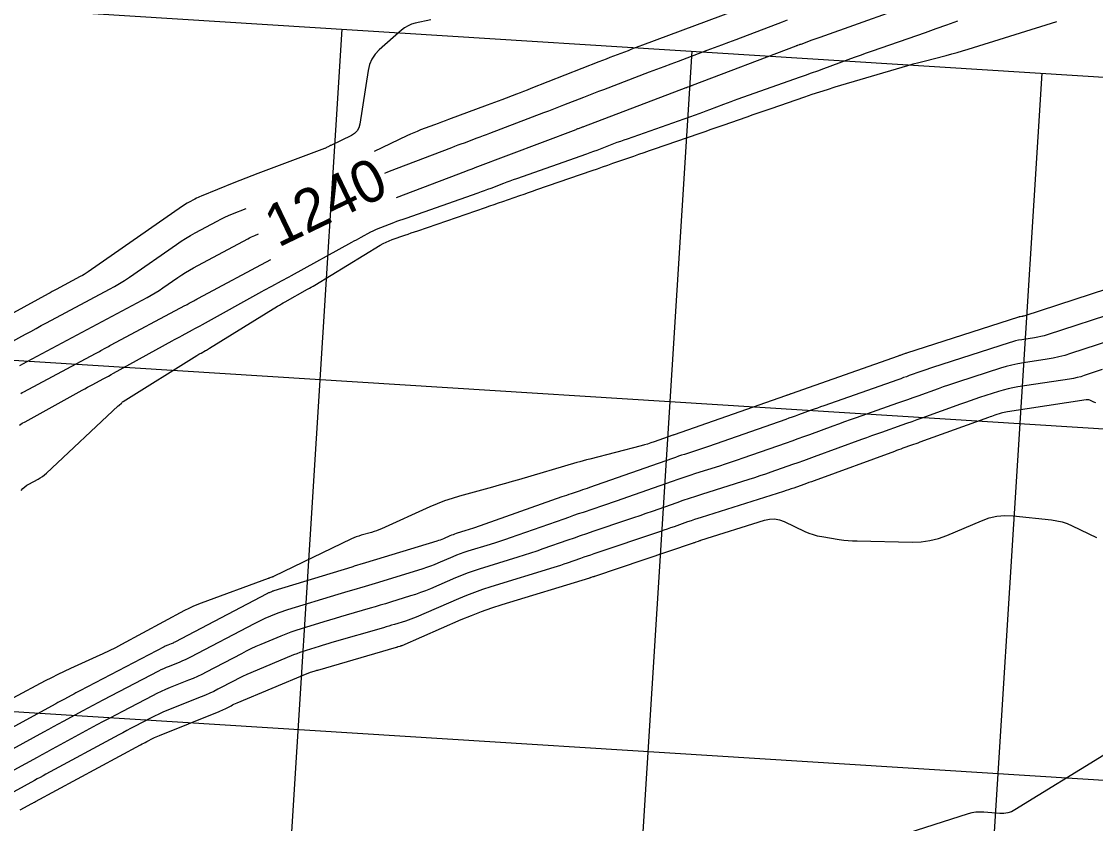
# Model space of a CAD drawing. Extents: x 658976 to 668721, y 639543 to 647196.
# Drawn here: x 662439.7 to 662592.9, y 641935.7 to 642050 of the extents above; entities that cross this region are included whole.
import ezdxf

# ---------------------------------------------------------------- set-up
doc = ezdxf.new("R2010")
doc.units = 0
for name, color, linetype in [('Ex_Contour Labels', 7, 'Continuous'), ('Ex_Major Contours', 7, 'Continuous'), ('Ex_Minor Contours', 7, 'Continuous'), ('R_Grid', 7, 'Continuous')]:
    doc.layers.add(name, color=color, linetype=linetype)

msp = doc.modelspace()

# ---------------------------------------------------------------- linework, layer by layer
at = {"layer": 'Ex_Major Contours'}
for points in [[(662491.52, 642028.41), (662491.94, 642028.59), (662492.57, 642028.85), (662493.2, 642029.1), (662501.06, 642032.09), (662501.51, 642032.26), (662501.96, 642032.43), (662502.41, 642032.6), (662502.86, 642032.76), (662504.67, 642033.43), (662505.12, 642033.6), (662505.57, 642033.76), (662506.02, 642033.93), (662506.47, 642034.1), (662514.21, 642037.05), (662514.92, 642037.32), (662515.63, 642037.59), (662516.34, 642037.87), (662517.05, 642038.15), (662519.89, 642039.26), (662520.6, 642039.54), (662521.31, 642039.81), (662522.02, 642040.09), (662522.73, 642040.36), (662529.28, 642042.85), (662530.3, 642043.24), (662531.33, 642043.63), (662532.36, 642044.01), (662533.38, 642044.4), (662537.5, 642045.93), (662538.52, 642046.31), (662539.55, 642046.7), (662540.58, 642047.09), (662541.6, 642047.48), (662548.24, 642050), (662548.92, 642050.26)], [(662439.47, 642001.02), (662439.99, 642001.3), (662440.51, 642001.58), (662457.63, 642010.7), (662458.2, 642011.02), (662458.77, 642011.35), (662459.32, 642011.7), (662459.86, 642012.07), (662462.01, 642013.56), (662462.55, 642013.93), (662463.11, 642014.28), (662463.67, 642014.61), (662464.24, 642014.93), (662471.98, 642019.07), (662472.23, 642019.2), (662472.48, 642019.32), (662472.73, 642019.43), (662472.99, 642019.54), (662473.5, 642019.75)], [(662593.83, 642000.41), (662591.26, 641999.57), (662590.75, 641999.41), (662590.23, 641999.28), (662589.7, 641999.17), (662589.17, 641999.07), (662581.78, 641997.94), (662581.08, 641997.82), (662580.39, 641997.68), (662579.7, 641997.5), (662579.02, 641997.3), (662576.32, 641996.42), (662575.64, 641996.2), (662574.97, 641995.98), (662574.3, 641995.74), (662573.63, 641995.51), (662568.07, 641993.5), (662567.36, 641993.24), (662566.65, 641992.98), (662565.93, 641992.73), (662565.22, 641992.48), (662562.35, 641991.47), (662561.64, 641991.22), (662560.92, 641990.97), (662560.21, 641990.71), (662559.5, 641990.45), (662552.74, 641987.98), (662551.97, 641987.7), (662551.2, 641987.42), (662550.42, 641987.15), (662549.65, 641986.87), (662546.55, 641985.79), (662545.78, 641985.52), (662545, 641985.26), (662544.22, 641985), (662543.44, 641984.75), (662536.68, 641982.62), (662535.8, 641982.33), (662534.91, 641982.04), (662534.03, 641981.74), (662533.15, 641981.44), (662529.63, 641980.2), (662528.75, 641979.89), (662527.87, 641979.59), (662526.99, 641979.28), (662526.1, 641978.99), (662521.16, 641977.32), (662520.27, 641977.02), (662519.38, 641976.71), (662518.5, 641976.4), (662517.61, 641976.09), (662514.06, 641974.85), (662513.18, 641974.54), (662512.28, 641974.24), (662511.39, 641973.95), (662510.49, 641973.67), (662504.99, 641971.99), (662504.13, 641971.71), (662503.28, 641971.41), (662502.43, 641971.09), (662501.6, 641970.74), (662498.01, 641969.19), (662497.32, 641968.9), (662496.62, 641968.63), (662495.91, 641968.38), (662495.19, 641968.15), (662492.32, 641967.27), (662491.6, 641967.05), (662490.87, 641966.83), (662490.15, 641966.62), (662489.43, 641966.41), (662486, 641965.41), (662485.21, 641965.18), (662484.41, 641964.95), (662483.62, 641964.71), (662482.83, 641964.47), (662479.57, 641963.47), (662478.84, 641963.24), (662478.11, 641962.98), (662477.39, 641962.71), (662476.68, 641962.43), (662473.84, 641961.24), (662473.13, 641960.93), (662472.43, 641960.61), (662471.74, 641960.28), (662471.06, 641959.93), (662466.05, 641957.3), (662465.43, 641956.98), (662464.8, 641956.68), (662464.16, 641956.4), (662463.51, 641956.13), (662460.91, 641955.09), (662460.26, 641954.82), (662459.62, 641954.54), (662458.99, 641954.24), (662458.37, 641953.93), (662454.11, 641951.71), (662453.2, 641951.23), (662452.29, 641950.75), (662451.37, 641950.26), (662450.46, 641949.77), (662444.68, 641946.65), (662443.99, 641946.28), (662443.3, 641945.9), (662442.61, 641945.53), (662441.92, 641945.15), (662433.56, 641940.6)]]:
    msp.add_lwpolyline(points, dxfattribs=at)
at = {"layer": 'Ex_Minor Contours'}
for points in [[(662490.02, 642031.53), (662494.72, 642033.78), (662495.2, 642034), (662495.69, 642034.22), (662496.18, 642034.42), (662496.67, 642034.62), (662498.66, 642035.37), (662499.16, 642035.56), (662499.66, 642035.75), (662500.16, 642035.93), (662500.65, 642036.12), (662506.16, 642038.14), (662506.68, 642038.34), (662507.2, 642038.53), (662507.72, 642038.72), (662508.24, 642038.92), (662510.32, 642039.71), (662510.84, 642039.91), (662511.36, 642040.11), (662511.88, 642040.31), (662512.4, 642040.52), (662522.09, 642044.33), (662522.61, 642044.53), (662523.13, 642044.73), (662523.65, 642044.93), (662524.16, 642045.13), (662526.24, 642045.92), (662526.76, 642046.12), (662527.28, 642046.31), (662527.8, 642046.51), (662528.32, 642046.7), (662543.14, 642052.23)], [(662493.18, 642024.97), (662503.07, 642028.72), (662503.18, 642028.76), (662503.29, 642028.81), (662503.41, 642028.85), (662503.52, 642028.89), (662503.97, 642029.05), (662504.08, 642029.09), (662504.2, 642029.13), (662504.31, 642029.17), (662504.42, 642029.21), (662518.78, 642034.66), (662518.87, 642034.7), (662518.96, 642034.73), (662519.06, 642034.77), (662519.15, 642034.8), (662519.53, 642034.93), (662519.63, 642034.97), (662519.72, 642035), (662519.81, 642035.04), (662519.91, 642035.07), (662534.48, 642040.61), (662534.56, 642040.64), (662534.63, 642040.67), (662534.71, 642040.7), (662534.78, 642040.72), (662535.09, 642040.83), (662535.17, 642040.86), (662535.24, 642040.89), (662535.32, 642040.91), (662535.39, 642040.94), (662550.19, 642046.57), (662550.24, 642046.59), (662550.3, 642046.61), (662550.36, 642046.64), (662550.42, 642046.66), (662550.65, 642046.74), (662550.71, 642046.76), (662550.76, 642046.78), (662550.82, 642046.8), (662550.88, 642046.82), (662552.47, 642047.4), (662552.75, 642047.51), (662553.04, 642047.61), (662553.32, 642047.71), (662553.61, 642047.82), (662569.33, 642053.47)], [(662498.06, 642050.27), (662495.86, 642049.79), (662495.32, 642049.63), (662494.82, 642049.42), (662494.34, 642049.14), (662493.91, 642048.8), (662490.73, 642045.99), (662490.13, 642045.36), (662489.66, 642044.66), (662489.33, 642043.88), (662489.12, 642043.04), (662487.95, 642035.4), (662487.81, 642034.88), (662487.56, 642034.43), (662487.21, 642034.07), (662486.75, 642033.78), (662483.82, 642032.38), (662483.74, 642032.34), (662483.67, 642032.3), (662483.59, 642032.26), (662483.52, 642032.22), (662483.21, 642032.06), (662483.14, 642032.02), (662483.06, 642031.99), (662482.98, 642031.95), (662482.9, 642031.92), (662473.39, 642028.36), (662472.53, 642028.04), (662471.68, 642027.71), (662470.82, 642027.37), (662469.97, 642027.03), (662465.34, 642025.16), (662465.11, 642025.06), (662464.88, 642024.96), (662464.65, 642024.85), (662464.43, 642024.73), (662463.54, 642024.25), (662463.32, 642024.13), (662463.1, 642024), (662462.89, 642023.87), (662462.68, 642023.73), (662449.19, 642014.34), (662448.92, 642014.16), (662448.65, 642013.99), (662448.38, 642013.83), (662448.09, 642013.67), (662444.67, 642011.84), (662444.38, 642011.69), (662444.09, 642011.54), (662443.8, 642011.38), (662443.52, 642011.23), (662430.08, 642003.91)], [(662439.4, 641992.52), (662439.81, 641992.76), (662440.21, 641992.99), (662448.37, 641997.49), (662448.74, 641997.7), (662449.11, 641997.9), (662449.48, 641998.1), (662449.86, 641998.3), (662451.35, 641999.1), (662451.73, 641999.3), (662452.1, 641999.5), (662452.47, 641999.7), (662452.84, 641999.91), (662461.17, 642004.51), (662461.53, 642004.71), (662461.89, 642004.91), (662462.26, 642005.1), (662462.62, 642005.3), (662464.08, 642006.07), (662464.44, 642006.27), (662464.8, 642006.46), (662465.16, 642006.66), (662465.53, 642006.86), (662473.97, 642011.53), (662474.33, 642011.72), (662474.68, 642011.92), (662475.03, 642012.11), (662475.38, 642012.3), (662476.8, 642013.05), (662477.15, 642013.24), (662477.51, 642013.43), (662477.86, 642013.62), (662478.21, 642013.82), (662486.79, 642018.56), (662487.13, 642018.75), (662487.47, 642018.93), (662487.81, 642019.12), (662488.15, 642019.3), (662489.53, 642020.03), (662489.87, 642020.21), (662490.22, 642020.38), (662490.58, 642020.53), (662490.94, 642020.67), (662492.81, 642021.38), (662493.24, 642021.55), (662493.67, 642021.71), (662494.11, 642021.86), (662494.54, 642022.02), (662504.83, 642025.63), (662505.29, 642025.8), (662505.75, 642025.96), (662506.21, 642026.13), (662506.67, 642026.3), (662508.5, 642027), (662508.96, 642027.17), (662509.41, 642027.34), (662509.87, 642027.51), (662510.33, 642027.67), (662520.33, 642031.19), (662520.81, 642031.36), (662521.3, 642031.53), (662521.78, 642031.71), (662522.26, 642031.89), (662524.19, 642032.62), (662524.67, 642032.81), (662525.15, 642032.98), (662525.64, 642033.16), (662526.12, 642033.33), (662535.82, 642036.75), (662536.33, 642036.93), (662536.84, 642037.11), (662537.35, 642037.3), (662537.85, 642037.49), (662539.87, 642038.26), (662540.38, 642038.45), (662540.89, 642038.64), (662541.4, 642038.82), (662541.9, 642039.01), (662550.64, 642042.08), (662551.51, 642042.39), (662552.38, 642042.7), (662553.25, 642043.02), (662554.12, 642043.34), (662557.6, 642044.61), (662558.47, 642044.93), (662559.34, 642045.24), (662560.21, 642045.55), (662561.08, 642045.86), (662568.6, 642048.47), (662570.14, 642049.01), (662571.68, 642049.56), (662573.21, 642050.12)], [(662439.66, 641983.2), (662439.9, 641983.47), (662440.17, 641983.71), (662440.46, 641983.93), (662440.77, 641984.11), (662442.06, 641984.81), (662442.38, 641984.99), (662442.68, 641985.19), (662442.97, 641985.41), (662443.25, 641985.66), (662453.48, 641995.23), (662453.49, 641995.24), (662453.51, 641995.25), (662453.52, 641995.26), (662453.53, 641995.27), (662453.58, 641995.3), (662453.59, 641995.31), (662453.6, 641995.31), (662453.62, 641995.32), (662453.63, 641995.33), (662453.94, 641995.65), (662453.99, 641995.7), (662454.05, 641995.76), (662454.12, 641995.8), (662454.18, 641995.85), (662464.72, 642002.43), (662464.87, 642002.52), (662465.01, 642002.61), (662465.16, 642002.7), (662465.31, 642002.78), (662465.92, 642003.12), (662466.07, 642003.2), (662466.22, 642003.29), (662466.37, 642003.37), (662466.52, 642003.46), (662476.22, 642009.46), (662476.49, 642009.62), (662476.76, 642009.78), (662477.03, 642009.94), (662477.3, 642010.09), (662480.51, 642011.87), (662480.77, 642012.02), (662481.02, 642012.16), (662481.28, 642012.31), (662481.53, 642012.47), (662490.85, 642018.13), (662491.26, 642018.37), (662491.69, 642018.58), (662492.13, 642018.77), (662492.57, 642018.94), (662494.39, 642019.57), (662494.84, 642019.73), (662495.29, 642019.89), (662495.75, 642020.05), (662496.2, 642020.2), (662505.89, 642023.54), (662506.5, 642023.75), (662507.11, 642023.96), (662507.72, 642024.17), (662508.33, 642024.38), (662510.76, 642025.23), (662511.37, 642025.44), (662511.98, 642025.65), (662512.58, 642025.86), (662513.19, 642026.07), (662521.09, 642028.79), (662521.83, 642029.05), (662522.57, 642029.31), (662523.31, 642029.56), (662524.05, 642029.82), (662527.02, 642030.86), (662527.76, 642031.12), (662528.5, 642031.37), (662529.24, 642031.63), (662529.98, 642031.89), (662536.34, 642034.08), (662537.2, 642034.37), (662538.05, 642034.67), (662538.91, 642034.97), (662539.77, 642035.27), (662543.19, 642036.46), (662544.04, 642036.76), (662544.9, 642037.06), (662545.76, 642037.35), (662546.61, 642037.65), (662551.39, 642039.3), (662552.47, 642039.67), (662553.56, 642040.02), (662554.65, 642040.36), (662555.74, 642040.7), (662565.31, 642043.53), (662566.09, 642043.76), (662566.87, 642043.98), (662567.65, 642044.19), (662568.43, 642044.4), (662571.57, 642045.2), (662572.35, 642045.41), (662573.13, 642045.63), (662573.91, 642045.85), (662574.68, 642046.09), (662587.34, 642050.05)], [(662434.21, 642002.16), (662440.28, 642005.47), (662441.03, 642005.87), (662441.78, 642006.28), (662442.53, 642006.68), (662443.29, 642007.08), (662452.24, 642011.86), (662452.98, 642012.26), (662453.7, 642012.69), (662454.41, 642013.14), (662455.1, 642013.6), (662461.79, 642018.26), (662462.45, 642018.7), (662463.11, 642019.12), (662463.79, 642019.53), (662464.49, 642019.91), (662467.62, 642021.59), (662468.15, 642021.86), (662468.69, 642022.12), (662469.23, 642022.37), (662469.78, 642022.6), (662471.74, 642023.39)], [(662439.61, 641997.03), (662439.82, 641997.15), (662440.03, 641997.26), (662450.25, 642002.71), (662450.44, 642002.81), (662450.63, 642002.91), (662450.81, 642003.02), (662451, 642003.12), (662451.74, 642003.53), (662451.93, 642003.63), (662452.11, 642003.73), (662452.3, 642003.83), (662452.49, 642003.93), (662462.98, 642009.53), (662463.15, 642009.62), (662463.31, 642009.7), (662463.47, 642009.79), (662463.63, 642009.88), (662464.28, 642010.24), (662464.44, 642010.33), (662464.6, 642010.42), (662464.76, 642010.5), (662464.93, 642010.59), (662475.25, 642016.09)], [(662599.36, 642013.51), (662582.63, 642008.05), (662582.57, 642008.03), (662582.5, 642008.02), (662582.44, 642008), (662582.37, 642007.99), (662582.11, 642007.95), (662582.05, 642007.94), (662581.99, 642007.93), (662581.92, 642007.91), (662581.86, 642007.89), (662565.89, 642002.75), (662565.8, 642002.72), (662565.7, 642002.69), (662565.6, 642002.65), (662565.5, 642002.62), (662565.11, 642002.48), (662565.01, 642002.44), (662564.91, 642002.41), (662564.81, 642002.37), (662564.72, 642002.34), (662549.46, 641996.98), (662549.4, 641996.96), (662549.33, 641996.93), (662549.27, 641996.91), (662549.2, 641996.89), (662548.94, 641996.79), (662548.87, 641996.77), (662548.81, 641996.74), (662548.74, 641996.72), (662548.67, 641996.7), (662532.76, 641991.11), (662532.75, 641991.11), (662532.73, 641991.1), (662532.72, 641991.1), (662532.71, 641991.1), (662532.65, 641991.08), (662532.64, 641991.08), (662532.63, 641991.07), (662532.61, 641991.07), (662532.6, 641991.06), (662529.9, 641990.11), (662529.45, 641989.96), (662528.99, 641989.81), (662528.53, 641989.68), (662528.06, 641989.55), (662520.75, 641987.67), (662520.28, 641987.55), (662519.81, 641987.42), (662519.34, 641987.29), (662518.88, 641987.16), (662510.57, 641984.73), (662509.65, 641984.46), (662508.73, 641984.2), (662507.81, 641983.94), (662506.89, 641983.68), (662502.18, 641982.38), (662501.1, 641982.06), (662500.03, 641981.7), (662498.98, 641981.29), (662497.94, 641980.85), (662491.03, 641977.72), (662490.68, 641977.57), (662490.33, 641977.44), (662489.98, 641977.32), (662489.61, 641977.21), (662488.16, 641976.81), (662487.8, 641976.7), (662487.44, 641976.58), (662487.09, 641976.44), (662486.75, 641976.28), (662475.63, 641970.92), (662475.57, 641970.89), (662475.51, 641970.86), (662475.44, 641970.84), (662475.38, 641970.81), (662475.12, 641970.72), (662475.05, 641970.7), (662474.99, 641970.68), (662474.92, 641970.66), (662474.86, 641970.63), (662465.31, 641967.12), (662464.71, 641966.89), (662464.13, 641966.64), (662463.55, 641966.36), (662462.97, 641966.07), (662453.98, 641961.25), (662453.09, 641960.78), (662452.19, 641960.33), (662451.29, 641959.89), (662450.37, 641959.47), (662446.71, 641957.81), (662445.8, 641957.39), (662444.89, 641956.96), (662443.99, 641956.5), (662443.1, 641956.04), (662438.49, 641953.57)], [(662596.48, 642008.81), (662585.95, 642005.37), (662585.52, 642005.24), (662585.07, 642005.12), (662584.62, 642005.03), (662584.17, 642004.95), (662582.36, 642004.67), (662581.9, 642004.59), (662581.46, 642004.5), (662581.01, 642004.38), (662580.57, 642004.25), (662569.62, 642000.72), (662569.2, 642000.59), (662568.79, 642000.45), (662568.37, 642000.3), (662567.96, 642000.16), (662566.31, 641999.56), (662565.9, 641999.41), (662565.49, 641999.27), (662565.08, 641999.12), (662564.66, 641998.97), (662554.1, 641995.26), (662553.65, 641995.1), (662553.2, 641994.94), (662552.75, 641994.78), (662552.3, 641994.62), (662550.5, 641993.96), (662550.05, 641993.8), (662549.6, 641993.64), (662549.15, 641993.48), (662548.7, 641993.32), (662537.67, 641989.45), (662537.25, 641989.3), (662536.82, 641989.16), (662536.39, 641989.02), (662535.96, 641988.88), (662534.25, 641988.34), (662533.82, 641988.2), (662533.39, 641988.06), (662532.96, 641987.91), (662532.54, 641987.77), (662520.68, 641983.6), (662520.36, 641983.48), (662520.03, 641983.37), (662519.7, 641983.26), (662519.38, 641983.15), (662518.07, 641982.71), (662517.74, 641982.6), (662517.42, 641982.48), (662517.09, 641982.37), (662516.76, 641982.26), (662504.31, 641977.87), (662504, 641977.77), (662503.7, 641977.66), (662503.39, 641977.56), (662503.08, 641977.47), (662501.71, 641977.05), (662501.47, 641976.97), (662501.24, 641976.89), (662501.01, 641976.8), (662500.78, 641976.71), (662499.88, 641976.31), (662499.65, 641976.22), (662499.42, 641976.13), (662499.19, 641976.05), (662498.95, 641975.97), (662488.77, 641972.87), (662488.6, 641972.82), (662488.44, 641972.77), (662488.28, 641972.72), (662488.11, 641972.67), (662487.46, 641972.48), (662487.29, 641972.43), (662487.13, 641972.38), (662486.97, 641972.33), (662486.8, 641972.28), (662475.69, 641968.88), (662475.6, 641968.86), (662475.51, 641968.83), (662475.43, 641968.79), (662475.34, 641968.76), (662475.01, 641968.62), (662474.93, 641968.58), (662474.84, 641968.55), (662474.76, 641968.51), (662474.68, 641968.46), (662461.55, 641961.57), (662461.43, 641961.51), (662461.31, 641961.45), (662461.18, 641961.39), (662461.06, 641961.34), (662460.56, 641961.14), (662460.44, 641961.09), (662460.32, 641961.04), (662460.19, 641960.98), (662460.07, 641960.92), (662448.01, 641954.63), (662447.73, 641954.48), (662447.44, 641954.33), (662447.15, 641954.18), (662446.87, 641954.02), (662445.73, 641953.41), (662445.44, 641953.25), (662445.16, 641953.1), (662444.87, 641952.95), (662444.59, 641952.79), (662425.46, 641942.38)], [(662594.99, 642004.56), (662589.28, 642002.69), (662588.47, 642002.44), (662587.64, 642002.23), (662586.81, 642002.05), (662585.97, 642001.9), (662582.6, 642001.39), (662581.76, 642001.24), (662580.93, 642001.06), (662580.1, 642000.85), (662579.29, 642000.61), (662573.34, 641998.69), (662572.61, 641998.46), (662571.88, 641998.21), (662571.15, 641997.96), (662570.42, 641997.7), (662567.52, 641996.65), (662566.79, 641996.39), (662566.07, 641996.13), (662565.34, 641995.87), (662564.61, 641995.61), (662558.73, 641993.55), (662557.89, 641993.25), (662557.06, 641992.95), (662556.23, 641992.65), (662555.39, 641992.35), (662552.06, 641991.13), (662551.23, 641990.83), (662550.4, 641990.53), (662549.56, 641990.23), (662548.73, 641989.94), (662542.59, 641987.78), (662541.75, 641987.49), (662540.91, 641987.21), (662540.07, 641986.93), (662539.22, 641986.66), (662535.84, 641985.59), (662534.99, 641985.32), (662534.15, 641985.05), (662533.31, 641984.76), (662532.47, 641984.47), (662525.33, 641981.96), (662524.64, 641981.72), (662523.95, 641981.48), (662523.26, 641981.24), (662522.56, 641981.01), (662519.79, 641980.07), (662519.09, 641979.84), (662518.4, 641979.6), (662517.71, 641979.36), (662517.02, 641979.12), (662509.41, 641976.44), (662508.7, 641976.19), (662507.99, 641975.95), (662507.28, 641975.72), (662506.56, 641975.5), (662503.35, 641974.52), (662502.8, 641974.34), (662502.26, 641974.15), (662501.72, 641973.95), (662501.19, 641973.72), (662499.08, 641972.81), (662498.55, 641972.59), (662498.02, 641972.38), (662497.48, 641972.19), (662496.93, 641972.02), (662490.63, 641970.09), (662490.14, 641969.95), (662489.66, 641969.8), (662489.17, 641969.66), (662488.69, 641969.52), (662486.74, 641968.95), (662486.26, 641968.81), (662485.77, 641968.67), (662485.29, 641968.52), (662484.8, 641968.37), (662477.63, 641966.18), (662477.22, 641966.05), (662476.81, 641965.91), (662476.41, 641965.75), (662476.01, 641965.59), (662474.42, 641964.93), (662474.03, 641964.76), (662473.64, 641964.58), (662473.25, 641964.39), (662472.87, 641964.2), (662463.8, 641959.43), (662463.43, 641959.24), (662463.05, 641959.06), (662462.67, 641958.89), (662462.29, 641958.74), (662460.74, 641958.12), (662460.35, 641957.96), (662459.97, 641957.79), (662459.59, 641957.61), (662459.22, 641957.42), (662451.28, 641953.28), (662450.57, 641952.91), (662449.86, 641952.54), (662449.16, 641952.16), (662448.45, 641951.78), (662445.64, 641950.26), (662444.93, 641949.88), (662444.23, 641949.5), (662443.53, 641949.12), (662442.82, 641948.74), (662429.51, 641941.49)], [(662592.89, 641995.7), (662592.76, 641995.72), (662592.64, 641995.76), (662592.52, 641995.81), (662592.04, 641996.04), (662591.92, 641996.09), (662591.79, 641996.12), (662591.67, 641996.13), (662591.54, 641996.12), (662580.3, 641994.4), (662580.07, 641994.36), (662579.84, 641994.31), (662579.61, 641994.25), (662579.39, 641994.19), (662578.5, 641993.9), (662578.28, 641993.83), (662578.05, 641993.75), (662577.83, 641993.68), (662577.61, 641993.6), (662567.83, 641990.06), (662567.53, 641989.95), (662567.22, 641989.84), (662566.92, 641989.73), (662566.61, 641989.63), (662565.39, 641989.2), (662565.09, 641989.09), (662564.78, 641988.98), (662564.48, 641988.87), (662564.18, 641988.76), (662552.72, 641984.57), (662552.36, 641984.44), (662552, 641984.31), (662551.63, 641984.18), (662551.27, 641984.05), (662549.82, 641983.54), (662549.46, 641983.42), (662549.1, 641983.3), (662548.73, 641983.18), (662548.37, 641983.06), (662536.64, 641979.36), (662536.15, 641979.2), (662535.67, 641979.04), (662535.18, 641978.88), (662534.7, 641978.71), (662532.76, 641978.03), (662532.27, 641977.86), (662531.79, 641977.69), (662531.3, 641977.52), (662530.82, 641977.36), (662521.31, 641974.15), (662520.84, 641973.99), (662520.37, 641973.83), (662519.89, 641973.67), (662519.42, 641973.5), (662517.53, 641972.84), (662517.06, 641972.67), (662516.58, 641972.51), (662516.11, 641972.36), (662515.63, 641972.21), (662506.63, 641969.46), (662505.45, 641969.08), (662504.29, 641968.67), (662503.15, 641968.23), (662502.01, 641967.76), (662495.99, 641965.15), (662495.61, 641964.99), (662495.23, 641964.84), (662494.84, 641964.71), (662494.45, 641964.58), (662492.88, 641964.1), (662492.49, 641963.98), (662492.09, 641963.86), (662491.7, 641963.75), (662491.31, 641963.63), (662483.98, 641961.5), (662483.52, 641961.37), (662483.06, 641961.23), (662482.6, 641961.1), (662482.14, 641960.96), (662480.3, 641960.4), (662479.85, 641960.25), (662479.4, 641960.09), (662478.95, 641959.92), (662478.5, 641959.75), (662472.42, 641957.2), (662471.82, 641956.94), (662471.22, 641956.66), (662470.63, 641956.38), (662470.05, 641956.08), (662467.72, 641954.86), (662467.14, 641954.56), (662466.55, 641954.28), (662465.95, 641954.01), (662465.34, 641953.76), (662460.45, 641951.81), (662459.86, 641951.57), (662459.27, 641951.31), (662458.69, 641951.03), (662458.12, 641950.74), (662455.84, 641949.56), (662455.27, 641949.26), (662454.71, 641948.96), (662454.14, 641948.66), (662453.57, 641948.35), (662443.19, 641942.75), (662442.78, 641942.53), (662442.37, 641942.3), (662441.95, 641942.08), (662441.54, 641941.86), (662436.56, 641939.15)], [(662439.53, 641937.67), (662441.16, 641938.56), (662441.3, 641938.63), (662441.43, 641938.71), (662441.57, 641938.78), (662441.71, 641938.85), (662456.68, 641946.94), (662456.9, 641947.06), (662457.13, 641947.17), (662457.35, 641947.29), (662457.57, 641947.41), (662458.46, 641947.87), (662458.68, 641947.98), (662458.91, 641948.09), (662459.14, 641948.19), (662459.37, 641948.29), (662467.87, 641951.68), (662468.09, 641951.77), (662468.31, 641951.86), (662468.52, 641951.96), (662468.73, 641952.07), (662469.58, 641952.51), (662469.79, 641952.62), (662470, 641952.73), (662470.22, 641952.82), (662470.44, 641952.92), (662480.43, 641957.11), (662480.56, 641957.16), (662480.68, 641957.2), (662480.81, 641957.25), (662480.93, 641957.29), (662481.44, 641957.44), (662481.57, 641957.48), (662481.7, 641957.52), (662481.83, 641957.56), (662481.95, 641957.6), (662493.18, 641960.86), (662493.25, 641960.87), (662493.31, 641960.89), (662493.38, 641960.91), (662493.44, 641960.93), (662493.71, 641961.01), (662493.77, 641961.04), (662493.84, 641961.06), (662493.9, 641961.08), (662493.97, 641961.11), (662502.42, 641964.78), (662503.86, 641965.38), (662505.31, 641965.94), (662506.78, 641966.45), (662508.27, 641966.93), (662520.76, 641970.75), (662520.82, 641970.77), (662520.88, 641970.79), (662520.94, 641970.81), (662521, 641970.83), (662521.23, 641970.91), (662521.29, 641970.93), (662521.35, 641970.95), (662521.41, 641970.97), (662521.47, 641970.99), (662535.53, 641975.73), (662535.62, 641975.76), (662535.71, 641975.79), (662535.8, 641975.82), (662535.89, 641975.86), (662536.24, 641975.98), (662536.33, 641976.01), (662536.42, 641976.04), (662536.51, 641976.07), (662536.6, 641976.1), (662545.67, 641978.96), (662546.39, 641979.12), (662547.09, 641979.14), (662547.79, 641979.02), (662548.47, 641978.77), (662551.41, 641977.36), (662551.99, 641977.11), (662552.59, 641976.9), (662553.19, 641976.73), (662553.81, 641976.61), (662556.32, 641976.22), (662556.95, 641976.13), (662557.58, 641976.06), (662558.21, 641976.02), (662558.85, 641975.99), (662566.72, 641975.84), (662568, 641975.88), (662569.24, 641976.05), (662570.47, 641976.35), (662571.66, 641976.79), (662576.6, 641978.88), (662577.7, 641979.27), (662578.81, 641979.51), (662579.95, 641979.61), (662581.11, 641979.56), (662586.57, 641978.99), (662587.34, 641978.88), (662588.09, 641978.7), (662588.81, 641978.46), (662589.52, 641978.15), (662593.02, 641976.47)], [(662594.04, 641945.46), (662581.37, 641937.67), (662580.87, 641937.41), (662580.34, 641937.23), (662579.8, 641937.15), (662579.23, 641937.15), (662576.93, 641937.34), (662576.36, 641937.36), (662575.79, 641937.33), (662575.23, 641937.23), (662574.68, 641937.09), (662561.2, 641932.76)]]:
    msp.add_lwpolyline(points, dxfattribs=at)
at = {"layer": 'R_Grid'}
for p, q in [((661637.1, 642102.2), (663134.15, 642008.18)), ((661633.97, 642052.3), (663131.02, 641958.27)), ((662469.76, 641799.41), (662485.43, 642048.92)), ((662519.66, 641796.28), (662535.33, 642045.78)), ((662569.56, 641793.14), (662585.23, 642042.65)), ((661630.83, 642002.39), (663127.88, 641908.37))]:
    msp.add_line(p, q, dxfattribs=at)

# ---------------------------------------------------------------- texts
at = {"layer": 'Ex_Contour Labels'}
msp.add_text('1240', height=6, rotation=25.6649, dxfattribs=at).set_placement((662476.3, 642017.76))

doc.saveas('drawing.dxf')
